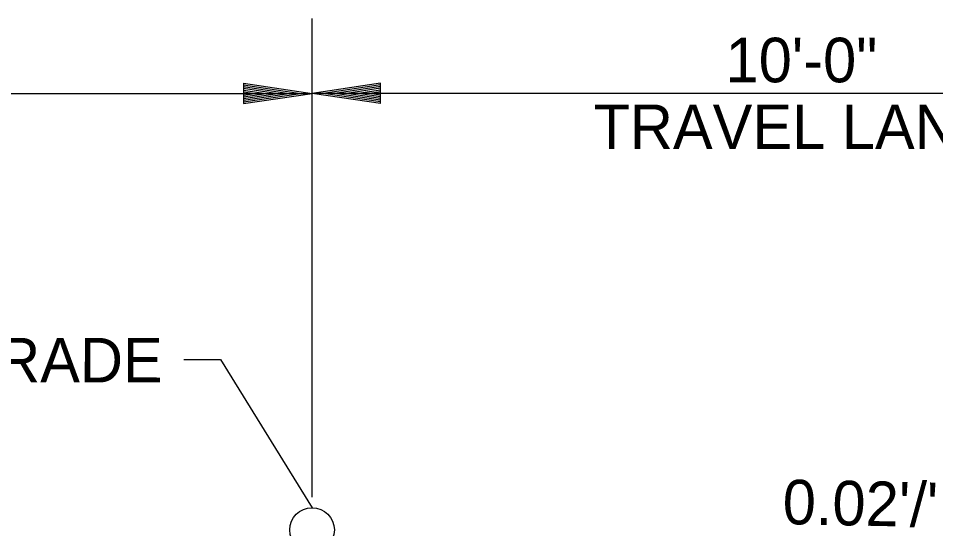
# Model space of a CAD drawing. Extents: x 1373719 to 1374161, y 379835 to 380167.
# Drawn here: x 1373961.07 to 1373974.45, y 379976.64 to 379984.09 of the extents above; entities that cross this region are included whole.
import ezdxf

# ---------------------------------------------------------------- set-up
doc = ezdxf.new("R2010")
doc.units = 0
doc.layers.add('CL Construction', color=7, linetype='Continuous')
doc.layers.add('GREEN_TXT', color=7, linetype='Continuous')

msp = doc.modelspace()

# ---------------------------------------------------------------- linework, layer by layer
at = {"layer": 'CL Construction'}
msp.add_line((1373965.355, 379977.1), (1373965.355, 379984.087), dxfattribs=at)
at = {"layer": 'GREEN_TXT'}
for p, q in [((1373964.355, 379983.142), (1373965.355, 379982.992)), ((1373964.355, 379983.142), (1373964.355, 379982.842)), ((1373964.355, 379983.117), (1373965.188, 379982.992)), ((1373964.355, 379983.091), (1373965.016, 379982.992)), ((1373964.355, 379983.066), (1373964.849, 379982.992)), ((1373964.355, 379983.04), (1373964.68, 379982.992)), ((1373964.355, 379983.015), (1373964.513, 379982.992)), ((1373966.355, 379983.142), (1373965.355, 379982.992)), ((1373966.355, 379983.117), (1373965.522, 379982.992)), ((1373966.355, 379983.091), (1373965.694, 379982.992)), ((1373966.355, 379983.066), (1373965.86, 379982.992)), ((1373966.355, 379983.041), (1373966.03, 379982.992)), ((1373966.355, 379983.015), (1373966.197, 379982.992)), ((1373966.355, 379982.842), (1373966.355, 379983.142)), ((1373948.855, 379982.992), (1373965.355, 379982.992)), ((1373964.355, 379982.842), (1373965.355, 379982.992)), ((1373964.355, 379982.943), (1373964.68, 379982.992)), ((1373964.355, 379982.892), (1373965.016, 379982.992)), ((1373964.355, 379982.867), (1373965.188, 379982.992)), ((1373964.355, 379982.917), (1373964.849, 379982.992)), ((1373964.355, 379982.968), (1373964.513, 379982.992)), ((1373981.855, 379982.992), (1373965.355, 379982.992)), ((1373966.355, 379982.842), (1373965.355, 379982.992)), ((1373966.355, 379982.867), (1373965.522, 379982.992)), ((1373966.355, 379982.892), (1373965.694, 379982.992)), ((1373966.355, 379982.917), (1373965.86, 379982.992)), ((1373966.355, 379982.943), (1373966.03, 379982.992)), ((1373966.355, 379982.968), (1373966.197, 379982.992))]:
    msp.add_line(p, q, dxfattribs=at)
msp.add_lwpolyline([(1373963.482, 379979.106), (1373964.019, 379979.106), (1373965.355, 379976.944)], dxfattribs=at)
msp.add_circle((1373965.355, 379976.619), 0.325, dxfattribs=at)

# ---------------------------------------------------------------- texts
for s, p in [('10\'-0"', (1373971.388, 379983.154)), ('TRAVEL LANE', (1373969.461, 379982.179))]:
    msp.add_text(s, height=0.65, dxfattribs=at).set_placement(p)
for s, rotation, p in [('PROFILE GRADE', 359.98, (1373956.124, 379978.775)), ("0.02'/'", 358.8542, (1373972.216, 379976.705))]:
    msp.add_text(s, height=0.65, rotation=rotation, dxfattribs=at).set_placement(p)

doc.saveas('drawing.dxf')
